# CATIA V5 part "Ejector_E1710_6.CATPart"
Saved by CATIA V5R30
Part number: Vyhazovac_2.5x160_4
Nomenclature: E1710/2.5x160
Description: MEUSBURGER
Property "Material": "1.221"
Publications: "__DrillHole", "Base"
Bounding box of the stored display mesh (mm): x -2.499 to 2.499, y -2.499 to 2.499, z 0 to 152
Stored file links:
  E:\Bakalarka\Model\Forma_v7\Ejector_E1710_6.CATPart
  E:\dev\MoldDesign\intel_a\startup\components\MoldCatalog\Ejector\Meusburger\Ejector_E1710\TableE1710.txt
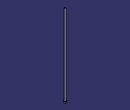
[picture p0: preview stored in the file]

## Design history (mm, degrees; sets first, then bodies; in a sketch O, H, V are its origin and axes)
Parameters
  Ref = "E1710/2.5x160" {design table}
  D1 = 2.5 mm {design table}
  D3 = 5 mm {design table}
  L = 160 mm {design table}
  L3 = 2 mm {design table}
  R = 0.3 mm {design table}
  k_d3 = 6 mm {design table}
  k_d1 = 2.7 mm {design table}
  k_F = 0.3 mm {design table}
  kl = 17 mm {design table}
  Mat = "1.221" {design table}
  HeatTreat = "ISO6751" {design table}
  Offset_Parting = 10 mm
  Anti_Rotation = "Normal"
  Anti_Rotation_D = 1.55 mm
  Anti_Rotation_D_Icut = 1.55 mm
  Add_Length_L = 0.0877 mm
  Add_Length_D3 = 0 mm
  SupplierRef = "Meusburger 2017"
  BmpRef = "F_MldEjectorD1"
  DrillHole_Length = 225 mm
  ValidationTest = false
  Anti_Rotation_D_min = 1.55 mm {= OffSet_D1 /2}
  Anti_Rotation_D_max = 2.425 mm {= D3/2-0.075mm}
  Anti_Rotation_D_ref = 1.55 mm {= Anti_Rotation_D}
  Anti_Rotation_D_Icut_ref = 1.55 mm {= Anti_Rotation_D_Icut}
  Anti_Rotation_Ref_Icut = 2.3246 mm
  Offset_L = 20 mm
  D = 2.5 mm {= D1}
  OffSet_D1 = 3.1 mm {= D1+2*R}
  OffSet_D3 = 6 mm {= D3+1mm}
  XG_Split = -122 mm
  YG_Split = 61 mm
  ZG_Split = -198 mm
  DirX_Split = 0 mm
  DirY_Split = 0 mm
  DirZ_Split = 1 mm
Set1 "BaseBody"
  Point1 "Base": (0, 0, 0)
  Plane1: type Offset, RefPlane xy-plane, Offset 225 {= DrillHole_Length}, reversed
  Sketch1 "Sketch.2" on xy-plane, origin (0, 0, 0), H (1, 0, 0), V (0, 1, 0)
    point P1 (-0.46, 1.1623)
    point P2 (0.46, 1.1623)
    construction line L1 (-0.46, 1.1623) -> (0.46, 1.1623)
    point P3 (0.46, -1.1623)
    line L2 (0.46, -1.1623) -> (0.46, 1.1623)
    point P4 (-0.46, -1.1623)
    construction line L3 (0.46, -1.1623) -> (-0.46, -1.1623)
    line L4 (-0.46, 1.1623) -> (-0.46, -1.1623)
    point P5 (-0.21, 1.1623)
    arc A1 centre (-0.21, 1.1623) radius 0.25 from (-0.21, 1.4123) to (-0.46, 1.1623) ccw
    point P7 (0.21, 1.1623)
    point P8 (0.21, 1.4123)
    arc A2 centre (0.21, 1.1623) radius 0.25 from (0.46, 1.1623) to (0.21, 1.4123) ccw
    line L5 (-0.21, 1.4123) -> (0.21, 1.4123)
    point P9 (-0.46, -1.1623)
    arc A3 centre (-0.21, -1.1623) radius 0.25 from (-0.46, -1.1623) to (-0.21, -1.4123) ccw
    point P11 (0.21, -1.4123)
    line L6 (-0.21, -1.4123) -> (0.21, -1.4123)
    point P12 (0.46, -1.1623)
    arc A4 centre (0.21, -1.1623) radius 0.25 from (0.21, -1.4123) to (0.46, -1.1623) ccw
    point P14 (-0.46, 1.1623)
    point P15 (-0.46, -1.1623)
    point P16 (0.46, 1.1623)
    point P17 (0.46, -1.1623)
    reference projected circle E1 centre (0, 0) radius 1.25 from edge [face of Shaft1 from Sketch2.L3 | face of Shaft1 from Sketch2.L4]
    reference projected circle E2 centre (0, 0) radius 1.25 from edge [face of Shaft1 from Sketch2.L3 | face of Shaft1 from Sketch2.L4]
    reference projected circle E3 centre (0, 0) radius 1.25 from edge [face of Shaft1 from Sketch2.L3 | face of Shaft1 from Sketch2.L4]
    reference projected circle E4 centre (0, 0) radius 1.25 from edge [face of Shaft1 from Sketch2.L3 | face of Shaft1 from Sketch2.L4]
    point P18 (-0.46, -1.1623)
    point P19 (-0.21, -1.4123)
    point P20 (0.21, -1.4123)
    point P21 (0.46, -1.1623)
    point P22 (-0.21, -1.4123)
    point P23 (0.21, -1.4123)
    distance P14 P15 = 2.3246 (reference)
    distance P16 P17 = 2.3246 (reference)
    distance L1 P14 = 0 (reference)
    radius A1 = 1.25
    distance L4 V = 1.56
    distance L2 V = 2.435
    distance L5 L6 = 5
    horizontal: L1 H, L3 H, L5 H
    vertical: L2 V, L4 V
    coincidence: P5 L1, P7 L1, P3 P12, P14 L4, P15 L4, P16 L2, P17 L2, P14 E1, P15 E2, P16 E3, P17 E4, P3 P21, P4 P18, P20 P23, P19 P22
    tangency: A1 L4, A2 L2, A2 L5, A1 L5
    symmetry: P1 P9 H, A1 A3 H, P8 P11 H, L5 L6 H, P2 P12 H, A2 A4 H
  DatumSurface1
Body1 "PartBody" (main body)
  Sketch2 "Sketch.1" on zx-plane, origin (0, 0, 0), H (-1, 0, 0), V (0, 0, 1)
    point P1 (0, 160)
    line L1 (1.25, 160) -> (0, 160)
    line L2 (1.25, 2) -> (1.25, 160)
    line L3 (2.5, 2) -> (1.25, 2)
    line L4 (2.5, 0) -> (2.5, 2)
    point P5 (0, 0)
    line L5 (0, 0) -> (2.5, 0)
    point P6 (0, 160)
    axis line L6 (0, 160) -> (0, 0)
    point P7 (0, 0)
    point P8 (1.25, 2)
    point P9 (1.25, 2)
    line L7 (0, 160) -> (0, 0)
    distance L5 L3 = 2 {= L3}
    distance L5 L1 = 160 {= L}
    distance L2 L6 = 1.25 {= D1 /2}
    distance L4 L6 = 2.5 {= D3 /2}
    coincidence: L6 P5, P1 L6, L5 H, L6 V, P7 O, P6 P1, P8 P9
    vertical: L2 V, L7 V
    horizontal: L1 H
  Shaft1 "Shaft.1": profile Sketch2, axis Sketch2.L6, angle 360
  Pocket1: profile face of Shaft1 from Sketch2.L1, direction along face of Shaft1 from Sketch2.L1 reversed, up to face of DatumSurface1
  Pocket2 "Pocket.1": profile Sketch1, direction (0, 0, 1), length 3, outer side, deactivated
  Pocket3 "Pocket.2": profile Sketch1, direction (0, 0, 1), length 3, outer side, deactivated
  Fillet1: radius 0.3 {= R}, on edge [face of Shaft1 from Sketch2.L2 | face of Shaft1 from Sketch2.L3]
Body2 "__DrillHole"
  Sketch3 "Sketch.3" on face of Shaft1, origin (0, 0, 0), H (1, 0, 0), V (0, -1, 0)
    point P1 (0, 0)
    reference projected point E1 (0, 0) from Point1
    coincidence: E1 P1
  Hole1 "Hole.1": placed by Sketch3, at (0, 0, 0) direction (0, 0, 1), diameter 3.1 {= OffSet_D1}, depth 140 {= L-Offset_L}
  Sketch4 "Sketch.4" on face of Shaft1, origin (0, 0, 0), H (1, 0, 0), V (0, -1, 0)
    point P1 (0, 0)
    reference projected point E1 (0, 0) from Point1
    coincidence: E1 P1
  Hole2 "Hole.2": placed by Sketch4, at (0, 0, 0) direction (0, 0, 1), diameter 2.5 {= D1}, depth 160 {= L}
  Sketch5 "Sketch.5" on face of Shaft1 from Sketch2.L3, origin (0, 0, 2), H (1, 0, 0), V (0, 1, 0)
    point P1 (0, 0)
    reference projected point E1 (0, 0) from Point1
    coincidence: E1 P1
  Hole3 "Hole.3": placed by Sketch5, at (0, 0, 2) direction (0, 0, -1), diameter 6 {= OffSet_D3}, depth 227 {= L3 +DrillHole_Length}
  Chamfer1: length 0.3 {= k_F}, angle 45, on edge [face of Hole1 | face of Hole3]
  Body3 "__Body.1"
    Pocket4 "Pocket.3": profile Sketch1, direction (0, 0, -1), length 225, opposite side length 2, deactivated
  Assemble1: tool Body3
  Chamfer2: length 0.3 {= k_F}, angle 45, on edge [start face of Pocket4 | face of Hole1], deactivated
  Body4 "__Body.2"
    Pocket5 "Pocket.4": profile Sketch1, direction (0, 0, -1), length 225, opposite side length 2, deactivated
  Assemble2: tool Body4
  Chamfer3: length 0.3 {= k_F}, angle 45, on edge [start face of Pocket5 | face of Hole1], deactivated
Current feature: Pocket1
Relations
  design table "TableE1710", configuration 134, drives Ref, D1, D3, L, L3, R, k_d3, k_d1, k_F, kl, Mat, HeatTreat
  Offset_L = 20mm (deactivated)
  rule "Cut_Head_rule":
    let sketch_cut (length)
    let PartBody_Pocket_Sketch (Boolean)
    let I_PartBody_Pocket (Boolean)
    let D_PartBody_Pocket (Boolean)
    let N_DrillHole_Hole (Boolean)
    let N_DrillHole_Hole_Sketch (Boolean)
    let I_DrillHole_Pocket (Boolean)
    let D_DrillHole_Pocket (Boolean)
    /* --------------------------------------------------------------------------------------*/
    if Anti_Rotation =="Normal"
    {
    	sketch_cut=Anti_Rotation_D_max
    	PartBody_Pocket_Sketch = false
    	I_PartBody_Pocket = false
    	D_PartBody_Pocket = false
    	N_DrillHole_Hole = true
    	N_DrillHole_Hole_Sketch = true
    	I_DrillHole_Pocket = false
    	D_DrillHole_Pocket = false
    	Chamfer1.Activity= true
    	Chamfer2.Activity= false
    	Chamfer3.Activity= false
    }
    if Anti_Rotation == "I_Cut"
    {
    	sketch_cut=Anti_Rotation_D_Icut_ref
    	PartBody_Pocket_Sketch = true
    	I_PartBody_Pocket = true
    	D_PartBody_Pocket = false
    	N_DrillHole_Hole = false
    	N_DrillHole_Hole_Sketch = false
    	I_DrillHole_Pocket = true
    	D_DrillHole_Pocket = false
    	Chamfer1.Activity= false
    	Chamfer2.Activity= true
    	Chamfer3.Activity= false
    }
    if Anti_Rotation =="D_Cut"
    {
    	sketch_cut=Anti_Rotation_D_max
    	PartBody_Pocket_Sketch = true
    	I_PartBody_Pocket = false
    	D_PartBody_Pocket = true
    	N_DrillHole_Hole = false
    	N_DrillHole_Hole_Sketch = false
    	I_DrillHole_Pocket = false
    	D_DrillHole_Pocket = true
    	Chamfer1.Activity= false
    	Chamfer2.Activity= false
    	Chamfer3.Activity= true
    }
    /* --------------------------------------------------------------------------------------*/
    Sketch1.distance(L2 V) = sketch_cut+0.01mm
    Sketch1.distance(L4 V) =Anti_Rotation_D_ref+0.01mm
    Sketch1.radius(A1) =D/2
    Pocket4.FirstLimit.Depth = DrillHole_Length
    Pocket5.FirstLimit.Depth = DrillHole_Length
    Pocket2.FirstLimit.Depth = L3+1mm
    Pocket3.FirstLimit.Depth = L3+1mm
    Pocket4.SecondLimit.Depth = L3
    Pocket5.SecondLimit.Depth =L3
    Pocket2.Activity = I_PartBody_Pocket
    Pocket3.Activity = D_PartBody_Pocket
    Sketch1.Activity =PartBody_Pocket_Sketch
    Hole3.Activity= N_DrillHole_Hole
    Sketch5.Activity = N_DrillHole_Hole_Sketch
    Pocket4.Activity = I_DrillHole_Pocket
    Pocket5.Activity  = D_DrillHole_Pocket
  rule "Anti_Rotation_Icut_constrain":
    let Ref1(length)
    let Ref2(length)
    let Ref3(length)
    let Diam1(length)
    let Diam2(length)
    let Add_Length_Lmin (length)
    Ref1=Sketch1.distance(P14 P15)
    Ref2=Sketch1.distance(P16 P17)
    Diam1=D
    Diam2=D3
    /* --------------------------------------------------------------------*/
    if Ref1 >Ref2
    	Anti_Rotation_Ref_Icut = Ref1
    else
    	Anti_Rotation_Ref_Icut  =Ref2
    Add_Length_D3 .InferiorRange=Anti_Rotation_Ref_Icut /2+Diam1/2 -Diam2/2
    if Add_Length_D3 .InferiorRange<0mm
    	Add_Length_D3 .InferiorRange=0mm
    if ValidationTest == "true"
    	Ref3   = 2*Add_Length_L +Anti_Rotation_Ref_Icut  +2*Diam1/2
    else
    	Ref3  =Diam2+2*Add_Length_D3
    if Ref3 <Diam2
    {
    	Ref3 =Diam2
    }
    /* --------------------------------------------------------------------*/
    Sketch1.distance(L5 L6) = Ref3
    Add_Length_L .InferiorRange=Diam2/2-Anti_Rotation_Ref_Icut/2-Diam1/2
    Add_Length_Lmin=Diam2/2-Anti_Rotation_Ref_Icut/2-Diam1/2
    if Add_Length_Lmin<0mm
    	Add_Length_L .InferiorRange=0mm
    else
    	Add_Length_L .InferiorRange=Add_Length_Lmin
